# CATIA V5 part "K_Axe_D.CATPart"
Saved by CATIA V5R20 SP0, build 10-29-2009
Part number: Axe_D
Bounding box of the stored display mesh (mm): x -7.5 to 7.5, y -7.49 to 7.49, z 0 to 50.817
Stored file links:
  G:\Khaled_CFAO_2011\ST2M\ST2M_GR2\echouteau\Khaled\CAD_ThinkMotion\K_Axe_D.CATPart
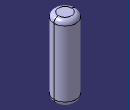
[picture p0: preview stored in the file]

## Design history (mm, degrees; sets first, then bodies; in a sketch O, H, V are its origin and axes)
AxisSystem1: origin (0, 0, 0), X (1, 0, 0), Y (0, 1, 0), Z (0, 0, 1)
Body1 (main body)
  Sketch1 on XY plane of AxisSystem1, origin (0, 0, 0), H (1, 0, 0), V (0, 1, 0)
    circle A1 centre (0, 0) radius 7.5
    radius A1 = 7.5
  Pad1: profile Sketch1, direction (0, 0, 1), length 50.817
  Fillet1: radius 3, on end face of Pad1
  Fillet2: radius 3, on edge [start face of Pad1 | face of Pad1 from Sketch1.A1]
